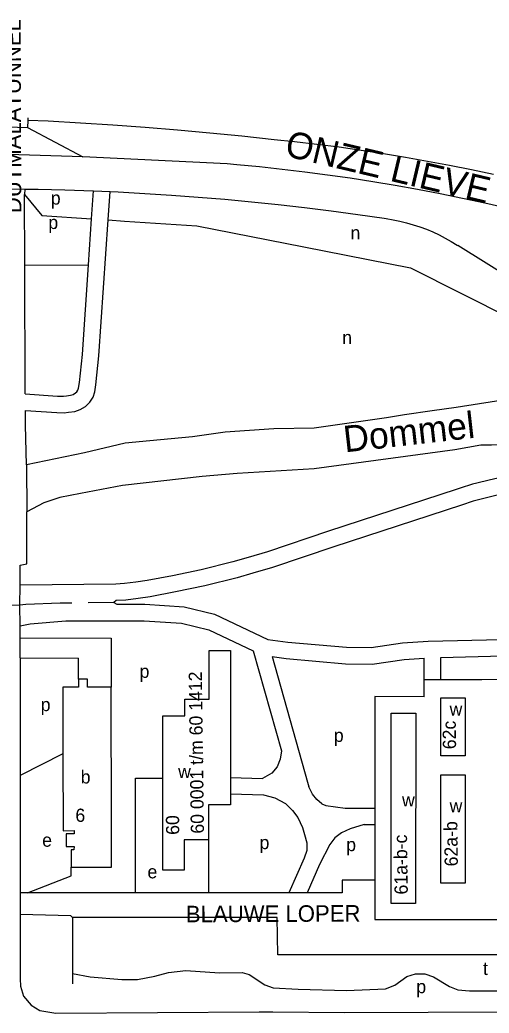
# Model space of a CAD drawing. Extents: x 161494 to 163033, y 383688 to 384862.
# Drawn here: x 162191.5 to 162333.3, y 384562 to 384862.5 of the extents above; entities that cross this region are included whole.
import ezdxf

# ---------------------------------------------------------------- set-up
doc = ezdxf.new("R2010")
doc.units = 0
for name, color, linetype in [('BLT_Basislijn', 7, 'Continuous'), ('BLT_Bebouwing', 7, 'Continuous'), ('BLT_Centroide', 7, 'Continuous'), ('BLT_Huisnummer', 7, 'Continuous'), ('BLT_Huisnummer_reeks', 7, 'Continuous'), ('BLT_Straatnaam', 7, 'Continuous'), ('BLT_Straatnaam_hoofdweg', 7, 'Continuous'), ('BLT_Vlakafsluiter', 7, 'Continuous'), ('BLT_Waternaam_spoorwegen', 7, 'Continuous')]:
    doc.layers.add(name, color=color, linetype=linetype)

msp = doc.modelspace()

# ---------------------------------------------------------------- linework, layer by layer
at = {"layer": 'BLT_Basislijn'}
for p, q in [((162164.95, 384830.77), (162193.87, 384829.95)), ((162193.95, 384832.1), (162193.87, 384829.95)), ((162193.98, 384832.82), (162193.95, 384832.1)), ((162193.04, 384788.24), (162192.97, 384809.66)), ((162277.31, 384793.82), (162309.6, 384787.43)), ((162361.38, 384770.68), (162323.86, 384794.28)), ((162193.04, 384788.24), (162212.27, 384788.42)), ((162193.17, 384749.37), (162193.04, 384788.24)), ((162309.6, 384787.43), (162372.08, 384756.07)), ((162193.21, 384739.92), (162193.19, 384744.36)), ((162193.55, 384727.84), (162193.68, 384713.61)), ((162191.56, 384685.46), (162191.57, 384691.44)), ((162219.95, 384686.26), (162212.2, 384686.14)), ((162191.57, 384679.12), (162191.56, 384685.46)), ((162191.57, 384675.52), (162191.57, 384679.12)), ((162191.62, 384669.43), (162191.57, 384675.52)), ((162262.07, 384671.61), (162270.57, 384641.34)), ((162191.62, 384669.43), (162209.28, 384669.42)), ((162191.62, 384669.43), (162191.63, 384633.84)), ((162209.28, 384663.01), (162209.28, 384669.42)), ((162313.76, 384662.96), (162313.76, 384669.4)), ((162318.76, 384662.95), (162318.76, 384669.58)), ((162313.76, 384657.7), (162313.76, 384662.96)), ((162313.76, 384662.96), (162318.76, 384662.95)), ((162318.76, 384662.95), (162331.14, 384662.94)), ((162331.14, 384662.94), (162356.15, 384663.06)), ((162204.53, 384640.48), (162191.63, 384633.84)), ((162191.63, 384633.84), (162191.64, 384598.4)), ((162255.21, 384633.3), (162264.87, 384633.01)), ((162298.77, 384624.02), (162298.77, 384619.02)), ((162295.59, 384619.02), (162298.77, 384619.02)), ((162298.77, 384619.02), (162298.77, 384602.26)), ((162248.55, 384614.42), (162248.55, 384598.4)), ((162282.08, 384606.95), (162278.33, 384598.4)), ((162191.64, 384598.4), (162191.64, 384597.18)), ((162193.87, 384598.4), (162191.64, 384598.4)), ((162191.64, 384597.18), (162191.65, 384591.8)), ((162226.44, 384598.4), (162193.87, 384598.4)), ((162248.55, 384598.4), (162226.44, 384598.4)), ((162272.86, 384598.4), (162248.55, 384598.4)), ((162207.44, 384590.95), (162207.44, 384573.99)), ((162207.44, 384573.99), (162207.44, 384570.89)), ((162268.03, 384562.35), (162289.61, 384562.22)), ((162289.61, 384562.22), (162472.53, 384562.61))]:
    msp.add_line(p, q, dxfattribs=at)
for points in [[(162268.39, 384826.24), (162258.64, 384827.27), (162248.89, 384828.22), (162239.13, 384829.1), (162229.36, 384829.89), (162219.59, 384830.61), (162209.81, 384831.24), (162200.03, 384831.8), (162193.95, 384832.1)], [(162334.63, 384815.68), (162328.01, 384817.1), (162321.37, 384818.43), (162314.72, 384819.69), (162308.06, 384820.87), (162301.38, 384821.97), (162294.69, 384823), (162287.98, 384823.94), (162281.27, 384824.8), (162274.55, 384825.59), (162268.39, 384826.24)], [(162210.54, 384821.02), (162123.33, 384823.8), (162055.58, 384824.15), (162020.49, 384823.11)], [(162254.14, 384818.93), (162210.54, 384821.02)], [(162338.74, 384805.52), (162332.01, 384807.05), (162325.27, 384808.5), (162318.52, 384809.87), (162311.74, 384811.17), (162304.96, 384812.38), (162298.16, 384813.52), (162291.35, 384814.58), (162284.52, 384815.55), (162277.68, 384816.45), (162270.84, 384817.27), (162263.99, 384818.01), (162257.12, 384818.67), (162254.14, 384818.93)], [(162186.14, 384811.38), (162188.96, 384811.37), (162193, 384811.31)], [(162193, 384811.31), (162192.97, 384809.66)], [(162192.97, 384809.66), (162198.14, 384803.35), (162213.22, 384802.31)], [(162193, 384811.31), (162197.04, 384811.25), (162205.12, 384811.06), (162213.79, 384810.75)], [(162213.22, 384802.31), (162213.79, 384810.75)], [(162213.79, 384810.75), (162218.79, 384810.53)], [(162218.2, 384801.97), (162218.79, 384810.53)], [(162218.79, 384810.53), (162221.26, 384810.42), (162229.33, 384809.99), (162237.39, 384809.47), (162245.45, 384808.88), (162253.5, 384808.2), (162261.54, 384807.45), (162269.57, 384806.61), (162277.6, 384805.7), (162285.62, 384804.7), (162293.62, 384803.63), (162301.62, 384802.48), (162302.27, 384802.38)], [(162193.19, 384744.36), (162202.68, 384743.68), (162204.91, 384743.65), (162206.21, 384743.76), (162208.09, 384744.03), (162209.73, 384744.64), (162211.37, 384745.53), (162212.69, 384746.81), (162213.67, 384748.39), (162214.14, 384749.94), (162214.52, 384752.08), (162215.39, 384760.84), (162218.2, 384801.97)], [(162212.27, 384788.42), (162213.22, 384802.31)], [(162218.2, 384801.97), (162223.18, 384801.62)], [(162223.18, 384801.62), (162245.03, 384800.2), (162277.31, 384793.82)], [(162302.27, 384802.38), (162304.33, 384802.04), (162306.38, 384801.61), (162308.42, 384801.11), (162310.43, 384800.53), (162312.42, 384799.87), (162314.38, 384799.14), (162316.32, 384798.33), (162318.22, 384797.45), (162320.08, 384796.49), (162321.91, 384795.47), (162323.7, 384794.38), (162323.86, 384794.28)], [(162193.17, 384749.37), (162202.89, 384748.68), (162204.74, 384748.65), (162205.65, 384748.73), (162206.84, 384748.9), (162207.64, 384749.2), (162208.39, 384749.61), (162208.77, 384749.97), (162209.08, 384750.47), (162209.27, 384751.11), (162209.57, 384752.77), (162210.41, 384761.25), (162212.27, 384788.42)], [(162352.79, 384749.77), (162347.84, 384748.65), (162344.2, 384748.3), (162335.61, 384747.17), (162323.38, 384745.26), (162316.09, 384744.22), (162307.76, 384743.01), (162302.29, 384742.05)], [(162302.29, 384742.05), (162280.48, 384738.93), (162268.33, 384738.75), (162253.57, 384737.71), (162243.68, 384736.32), (162230.84, 384735.11), (162223.38, 384734.41), (162211.05, 384731.46), (162193.55, 384727.84)], [(162193.55, 384727.84), (162193.21, 384739.92)], [(162342.71, 384734.12), (162334.11, 384733.78), (162330.82, 384733.78), (162323, 384732.39), (162280.47, 384726.65), (162257.2, 384725.26), (162246.61, 384724.39)], [(162246.61, 384724.39), (162222.56, 384721.61), (162209.89, 384719.18), (162203.64, 384717.97), (162198.78, 384716.4), (162193.68, 384713.61)], [(162337.25, 384724.06), (162335.97, 384723.82), (162334.69, 384723.55), (162333.41, 384723.27), (162332.14, 384722.98), (162330.87, 384722.66), (162329.61, 384722.33), (162328.35, 384721.98), (162327.1, 384721.61), (162325.85, 384721.23), (162324.6, 384720.83), (162323.37, 384720.41)], [(162323.37, 384720.41), (162284.85, 384707.79), (162266.34, 384701.59), (162260.55, 384699.84), (162255.94, 384698.52), (162246.28, 384696.12), (162237.63, 384694.31), (162230.04, 384692.91), (162226.61, 384692.35), (162223.11, 384691.94), (162220.51, 384691.8), (162191.57, 384691.44)], [(162338.19, 384719.15), (162336.97, 384718.92), (162335.76, 384718.67), (162334.54, 384718.4), (162333.34, 384718.12), (162332.13, 384717.82), (162330.93, 384717.51), (162329.73, 384717.17), (162328.54, 384716.83), (162327.35, 384716.46), (162326.17, 384716.08), (162325, 384715.68)], [(162191.57, 384691.44), (162191.6, 384697.51), (162193.66, 384697.92), (162193.68, 384713.61)], [(162325, 384715.68), (162286.43, 384703.05), (162267.89, 384696.83), (162261.97, 384695.05), (162257.25, 384693.69), (162247.39, 384691.24), (162238.59, 384689.4), (162230.89, 384687.98), (162227.3, 384687.4), (162223.6, 384686.97), (162220.67, 384686.8)], [(162220.67, 384686.8), (162219.95, 384686.26), (162220.83, 384685.67), (162229.27, 384685.67), (162241.18, 384684.93), (162250.36, 384682.68), (162266.46, 384675.07), (162272.51, 384674.26), (162290.25, 384672.71), (162297.71, 384672.56), (162307.17, 384673.99), (162314.91, 384674.48), (162336.96, 384675.07), (162344.86, 384676.63), (162377.04, 384684.84)], [(162207.19, 384686.06), (162203.73, 384686.01), (162193.29, 384685.64), (162191.56, 384685.46)], [(162191.57, 384679.12), (162194.66, 384679.76), (162205.38, 384680.67), (162229.11, 384680.67), (162240.42, 384679.97), (162248.68, 384677.94), (162262.07, 384671.61)], [(162191.57, 384675.52), (162219.11, 384675.43), (162219.11, 384660.61)], [(162318.76, 384669.58), (162337.51, 384670.08), (162345.96, 384671.75), (162356.15, 384674.35)], [(162267.76, 384669.85), (162278.44, 384631.84), (162278.82, 384630.43)], [(162267.76, 384669.85), (162271.97, 384669.29), (162289.99, 384667.71), (162298.04, 384667.56), (162307.7, 384669.01), (162313.76, 384669.4)], [(162313.76, 384657.7), (162298.77, 384657.75), (162298.77, 384624.02)], [(162270.57, 384641.34), (162270.24, 384638.86), (162269.29, 384636.46), (162267.64, 384634.61), (162264.87, 384633.01)], [(162226.44, 384598.4), (162226.44, 384633.04), (162234.71, 384633.03)], [(162282.8, 384625.33), (162281.29, 384626.62), (162280.01, 384628.27), (162278.82, 384630.43)], [(162255.21, 384628.29), (162265.16, 384628), (162268.62, 384627.13), (162271.77, 384625.41)], [(162271.77, 384625.41), (162273.91, 384623.26), (162275.51, 384621.22), (162276.94, 384618.18)], [(162282.8, 384625.33), (162284.01, 384624.77), (162289.84, 384624.02), (162298.77, 384624.02)], [(162276.94, 384618.18), (162277.53, 384616), (162278.21, 384613.47), (162278.21, 384611.23), (162277.48, 384608.91), (162272.86, 384598.4)], [(162295.59, 384619.02), (162291.33, 384617.74), (162288.75, 384616.49), (162286.75, 384615), (162285.22, 384613.03), (162282.08, 384606.95)], [(162193.87, 384598.4), (162207.03, 384603.48), (162207.02, 384606.16)], [(162298.77, 384602.26), (162288.9, 384602.26), (162288.9, 384598.4), (162278.33, 384598.4)], [(162298.77, 384602.26), (162298.77, 384590.27), (162376.17, 384590.27), (162376.17, 384597.18)], [(162207.44, 384590.95), (162206.93, 384591.47), (162191.65, 384591.8)], [(162191.65, 384591.8), (162191.65, 384572.4), (162191.76, 384570.14), (162192.61, 384567.15), (162194.91, 384564.35), (162197.54, 384562.76), (162202.4, 384561.98), (162263.85, 384562.38), (162268.03, 384562.35)], [(162410.73, 384580.75), (162410.73, 384579.6), (162269.46, 384579.6), (162269.33, 384590.95), (162207.44, 384590.95)], [(162207.44, 384573.99), (162212.73, 384572.95), (162222.38, 384572.13), (162227.07, 384572.13), (162232.36, 384573.14), (162236.42, 384574.32), (162241.66, 384574.92), (162251.89, 384574.14), (162258.75, 384574.25), (162260.85, 384573.72), (162265.55, 384570.51), (162268.1, 384569.61), (162275.59, 384569.21), (162290.21, 384568.85), (162302.04, 384569.29), (162304.84, 384570.4)], [(162304.84, 384570.4), (162308.45, 384573.06), (162311.11, 384573.86), (162313.89, 384573.9), (162316.52, 384573), (162321.41, 384570.01), (162323.89, 384569.03), (162327.46, 384568.68), (162352.01, 384568.73)]]:
    msp.add_lwpolyline(points, dxfattribs=at)
at = {"layer": 'BLT_Bebouwing'}
for p, q in [((162219.2, 384617.95), (162219.13, 384660.62)), ((162255.21, 384633.3), (162255.21, 384628.29)), ((162311.13, 384595.14), (162303.77, 384595.14))]:
    msp.add_line(p, q, dxfattribs=at)
for points in [[(162234.71, 384633.03), (162234.71, 384651.97), (162241.35, 384651.97), (162241.36, 384657.01), (162248.74, 384657), (162248.75, 384671.72), (162255.2, 384671.73), (162255.21, 384633.3)], [(162209.28, 384663.01), (162209.27, 384660.58), (162204.49, 384660.61), (162204.53, 384640.48)], [(162219.13, 384660.62), (162211.92, 384660.6), (162211.93, 384663.01), (162209.28, 384663.01)], [(162303.77, 384595.14), (162303.77, 384652.74), (162311.16, 384652.71), (162311.13, 384595.14)], [(162204.53, 384640.48), (162204.59, 384617.18), (162207.9, 384617.19), (162207.9, 384616.23), (162205.5, 384616.22), (162205.48, 384612.39), (162207.89, 384612.38), (162207.88, 384611.42), (162207.01, 384611.43), (162207.02, 384606.16)], [(162248.55, 384614.42), (162241.17, 384614.41), (162241.15, 384605.27), (162234.7, 384605.28), (162234.71, 384633.03)], [(162255.21, 384628.29), (162255.21, 384625.03), (162248.56, 384625.04), (162248.55, 384614.42)], [(162207.02, 384606.16), (162219.23, 384606.18), (162219.2, 384617.95)]]:
    msp.add_lwpolyline(points, dxfattribs=at)
for points in [[(162318.76, 384657.38), (162326.14, 384657.38), (162326.15, 384639.79), (162318.75, 384639.81)], [(162318.77, 384634.13), (162326.14, 384634.13), (162326.12, 384601.34), (162318.77, 384601.35)]]:
    msp.add_lwpolyline(points, close=True, dxfattribs=at)
at = {"layer": 'BLT_Vlakafsluiter'}
for p, q in [((162193.87, 384829.95), (162210.54, 384821.02)), ((162181.54, 384685.47), (162191.56, 384685.46)), ((162278.33, 384598.4), (162272.86, 384598.4))]:
    msp.add_line(p, q, dxfattribs=at)

# ---------------------------------------------------------------- texts
at = {"layer": 'BLT_Centroide'}
for s, p in [('p', (162200.87, 384806.6)), ('p', (162200.13, 384799.22)), ('n', (162291.45, 384796.08)), ('n', (162288.95, 384764.39)), ('p', (162227.7, 384663.41)), ('p', (162197.83, 384653.35)), ('w', (162321.4, 384651.97)), ('p', (162286.41, 384644.04)), ('b', (162209.91, 384631.46)), ('w', (162239.35, 384633.11)), ('w', (162307.02, 384624.5)), ('w', (162321.4, 384622.73)), ('e', (162198.27, 384612.33)), ('p', (162263.96, 384611.6)), ('p', (162290.15, 384610.98)), ('e', (162230.09, 384602.76)), ('t', (162331.5, 384573.51)), ('p', (162311.33, 384568.01))]:
    msp.add_text(s, height=4, dxfattribs=at).set_placement(p)
at = {"layer": 'BLT_Huisnummer'}
for s, rotation, p in [('62c', 90.77, (162323.37, 384641.85)), ('6', 359.77, (162208.3, 384619.86))]:
    msp.add_text(s, height=4, rotation=rotation, dxfattribs=at).set_placement(p)
at = {"layer": 'BLT_Huisnummer_reeks'}
for s, p in [('60 0001 t/m 60 1412', (162247.19, 384616.31)), ('60', (162239.72, 384615.94)), ('62a-b', (162323.91, 384606.4)), ('61a-b-c', (162308.77, 384597.89))]:
    msp.add_text(s, height=4, rotation=90.77, dxfattribs=at).set_placement(p)
at = {"layer": 'BLT_Straatnaam'}
for s, rotation, p in [('DUTMALATUNNEL', 90.1963, (162191.98, 384804.02)), ('BLAUWE LOPER', 0.2472, (162241.71, 384589.46))]:
    msp.add_text(s, height=5, rotation=rotation, dxfattribs=at).set_placement(p)
at = {"layer": 'BLT_Straatnaam_hoofdweg'}
msp.add_text('ONZE LIEVE VROUWESTRAAT', height=8, rotation=346.6603, dxfattribs=at).set_placement((162271.26, 384821.4))
at = {"layer": 'BLT_Waternaam_spoorwegen'}
msp.add_text('Dommel', height=8, rotation=6.4446, dxfattribs=at).set_placement((162289.77, 384731.62))

doc.saveas('drawing.dxf')
